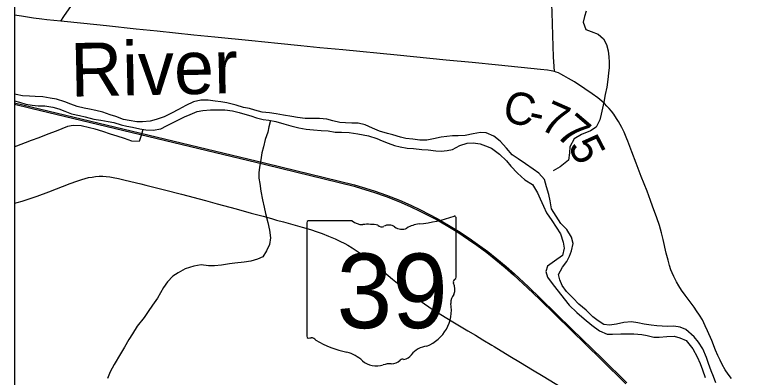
# Model space of a CAD drawing. Extents: x -7.5 to 53.5, y 0 to 22.
# Drawn here: x 2.1 to 3.39, y 17.82 to 18.461 of the extents above; entities that cross this region are included whole.
import ezdxf

# ---------------------------------------------------------------- set-up
doc = ezdxf.new("R2010")
doc.units = 0
for name, color, linetype in [('GM_X_Corporation', 7, 'Continuous'), ('GM_X_County_Road', 7, 'Continuous'), ('GM_X_County_Road_Text', 7, 'Continuous'), ('GM_X_Major_River', 7, 'Continuous'), ('GM_X_Major_River_Text', 7, 'Continuous'), ('GM_X_Minor_River', 7, 'Continuous'), ('GM_X_Rail_Line', 7, 'Continuous'), ('GM_X_State_Location', 7, 'Continuous'), ('GM_X_State_Route', 7, 'Continuous'), ('GM_X_State_Shield', 7, 'Continuous'), ('GM_X_Township_Road', 7, 'Continuous'), ('SH_Data', 7, 'Continuous')]:
    doc.layers.add(name, color=color, linetype=linetype)

msp = doc.modelspace()

# ---------------------------------------------------------------- linework, layer by layer
at = {"layer": 'GM_X_Corporation'}
msp.add_lwpolyline([(4.6087, 14.5302), (4.6021, 15.6139), (4.594, 15.8096), (4.5873, 16.3533), (4.5872, 16.3635), (4.5826, 16.8462), (4.5822, 16.8992), (4.577, 17.1178), (4.5749, 17.2575), (4.5771, 17.6201), (4.5718, 18.1276), (4.5696, 18.2604), (4.5565, 19.1354), (5.0411, 19.1401), (6.0424, 19.1527), (6.0433, 19.1527), (6.5522, 19.1561), (7.544, 19.1455), (8.414, 19.1709), (8.5159, 19.1718), (8.9, 19.1887), (8.9, 20.9), (2.1, 20.9), (2.1, 14.1)], dxfattribs=at)
at = {"layer": 'GM_X_County_Road'}
for points in [[(3.0531, 18.3609), (3.0527, 18.3697), (3.0516, 18.387), (3.0502, 18.4243), (3.0495, 18.446), (3.0491, 18.4647), (3.0481, 18.4957), (3.0475, 18.5174), (3.0463, 18.5516), (3.0457, 18.5827), (3.0453, 18.6044), (3.0449, 18.6137), (3.0444, 18.6167), (3.0437, 18.6196), (3.0427, 18.6224), (3.0412, 18.6249), (3.0393, 18.627), (3.037, 18.6288), (3.0361, 18.6293)], [(2.1814, 18.4499), (2.1571, 18.4524), (2.1481, 18.4534), (2.1333, 18.4552), (2.112, 18.4584), (2.1, 18.4606)], [(3.0531, 18.3609), (3.0472, 18.362), (3.0411, 18.363), (3.0288, 18.3647), (2.9545, 18.3721), (2.9082, 18.3768), (2.8618, 18.3812), (2.7752, 18.3896), (2.6794, 18.3991), (2.6391, 18.4029), (2.6051, 18.4062), (2.565, 18.4101), (2.5186, 18.4149), (2.4537, 18.4215), (2.4166, 18.425), (2.3517, 18.4319), (2.3146, 18.4358), (2.2621, 18.4415), (2.222, 18.4457), (2.1814, 18.4499)], [(3.0834, 18.3456), (3.078, 18.3487), (3.07, 18.3534), (3.0647, 18.3563), (3.0603, 18.3583), (3.0561, 18.36), (3.0531, 18.3609)], [(3.1827, 18.2375), (3.1809, 18.2421), (3.1762, 18.2536), (3.1722, 18.262), (3.1694, 18.2674), (3.1663, 18.2728), (3.163, 18.2781), (3.1578, 18.2857), (3.154, 18.2906), (3.15, 18.2954), (3.1458, 18.2999), (3.1415, 18.3043), (3.1369, 18.3084), (3.1297, 18.3142), (3.1196, 18.3215), (3.1068, 18.3302), (3.0888, 18.3424), (3.0834, 18.3456)], [(3.3657, 17.8181), (3.36, 17.8258), (3.3548, 17.8337), (3.3494, 17.8428), (3.3456, 17.8504), (3.3415, 17.8589), (3.3377, 17.8686), (3.3309, 17.8852), (3.3235, 17.9024), (3.3196, 17.9116), (3.3144, 17.9217), (3.3093, 17.9304), (3.3041, 17.9381), (3.2997, 17.9445), (3.2912, 17.9561), (3.2843, 17.9653), (3.2777, 17.9745), (3.2728, 17.982), (3.2686, 17.9891), (3.2643, 17.9983), (3.2609, 18.0053), (3.2588, 18.0106), (3.2564, 18.0182), (3.2538, 18.0272), (3.2507, 18.0399), (3.2453, 18.0639), (3.2422, 18.0758), (3.2387, 18.0888), (3.234, 18.1024), (3.2266, 18.1231), (3.2228, 18.133), (3.2167, 18.1492), (3.2066, 18.1752), (3.1978, 18.1986), (3.19, 18.2189), (3.1827, 18.2375)]]:
    msp.add_lwpolyline(points, dxfattribs=at)
at = {"layer": 'GM_X_Major_River'}
for points in [[(2.491, 18.3013), (2.4747, 18.3055), (2.4644, 18.3074), (2.4542, 18.3086), (2.4416, 18.3101), (2.4291, 18.3101), (2.4158, 18.3075), (2.4022, 18.3006), (2.3892, 18.2938), (2.3771, 18.287), (2.3642, 18.2805), (2.3501, 18.276), (2.3395, 18.2733), (2.3258, 18.2718), (2.316, 18.2722), (2.3023, 18.2741), (2.2924, 18.276), (2.2788, 18.2813), (2.2685, 18.2844), (2.2556, 18.2889), (2.2435, 18.292), (2.2325, 18.2943), (2.223, 18.2962), (2.2105, 18.2992), (2.1995, 18.3034), (2.1888, 18.3072), (2.174, 18.3117), (2.1627, 18.314), (2.1498, 18.3159), (2.1361, 18.3167), (2.1262, 18.3171), (2.1141, 18.3179), (2.1027, 18.3201), (2.1, 18.3211)], [(2.1, 18.309), (2.1087, 18.3068), (2.1201, 18.3034), (2.1311, 18.3011), (2.1414, 18.3004), (2.1532, 18.3), (2.1672, 18.2981), (2.1782, 18.295), (2.1888, 18.2909), (2.2006, 18.2859), (2.2146, 18.2829), (2.2245, 18.2806), (2.2397, 18.2768), (2.2522, 18.2749), (2.2651, 18.2726), (2.275, 18.2707), (2.2879, 18.2669), (2.2981, 18.2642), (2.308, 18.2627), (2.3213, 18.2593), (2.3319, 18.2578), (2.3448, 18.2574), (2.3581, 18.2596), (2.3683, 18.265), (2.3904, 18.276), (2.3999, 18.2805), (2.4097, 18.2851), (2.4223, 18.2904), (2.4321, 18.2919), (2.4458, 18.293), (2.4568, 18.2934), (2.4712, 18.2934), (2.4845, 18.2915), (2.4963, 18.2884), (2.5065, 18.2854), (2.5172, 18.2823), (2.527, 18.2789), (2.5388, 18.2759), (2.549, 18.2747), (2.5612, 18.2725), (2.5752, 18.2686), (2.5877, 18.2648), (2.6018, 18.2614), (2.6147, 18.2591), (2.628, 18.2576), (2.6412, 18.2568), (2.6534, 18.2561), (2.6663, 18.2538)], [(3.048, 18.1181), (3.0454, 18.1321), (3.0431, 18.1435), (3.0389, 18.1568), (3.0355, 18.1701), (3.0257, 18.1811), (3.0158, 18.1883), (3.0022, 18.1978), (2.9889, 18.2066), (2.9783, 18.2138), (2.9684, 18.2256), (2.9574, 18.2377), (2.946, 18.2464), (2.9328, 18.2522), (2.9229, 18.2529), (2.9096, 18.2506), (2.8956, 18.248), (2.883, 18.2469), (2.8732, 18.2469), (2.8629, 18.2461), (2.8534, 18.245), (2.8394, 18.2419), (2.828, 18.2397), (2.8155, 18.2397), (2.8033, 18.2412), (2.7908, 18.2427), (2.7813, 18.245), (2.768, 18.2488), (2.7582, 18.2515), (2.7441, 18.2553), (2.732, 18.2606), (2.7191, 18.2667), (2.7069, 18.2693), (2.6952, 18.2697), (2.6842, 18.2701), (2.6743, 18.2705), (2.6618, 18.2735), (2.6511, 18.2766), (2.6382, 18.2777), (2.6265, 18.2777), (2.6132, 18.2781), (2.5995, 18.2797), (2.5896, 18.2816), (2.5745, 18.2838), (2.5619, 18.2861), (2.5498, 18.2876), (2.5373, 18.2892), (2.5244, 18.2926), (2.5145, 18.2953), (2.5043, 18.2975), (2.491, 18.3013)], [(2.6663, 18.2538), (2.6773, 18.2538), (2.691, 18.253), (2.7058, 18.2507), (2.7156, 18.2488), (2.7251, 18.2469), (2.7395, 18.2424), (2.749, 18.2382), (2.7596, 18.234), (2.7707, 18.2302), (2.7805, 18.2275), (2.793, 18.2256), (2.8044, 18.2245), (2.8188, 18.2233), (2.8302, 18.2222), (2.8435, 18.2207), (2.853, 18.2199), (2.8636, 18.2214), (2.8731, 18.2229), (2.8864, 18.2301), (2.8993, 18.2343), (2.9096, 18.2351), (2.9221, 18.2328), (2.9316, 18.2294), (2.9418, 18.2252), (2.9563, 18.2149), (2.9684, 18.2028), (2.976, 18.1933), (2.9877, 18.1811), (3.001, 18.1697), (3.0146, 18.1614), (3.0234, 18.1465), (3.0279, 18.1359), (3.034, 18.123), (3.0393, 18.1112), (3.0487, 18.0975)], [(3.3381, 17.8108), (3.3338, 17.8217), (3.33, 17.8316), (3.3254, 17.8445), (3.3216, 17.8551), (3.3154, 17.8706), (3.3078, 17.8824), (3.2998, 17.8922), (3.285, 17.905), (3.2751, 17.9088), (3.2641, 17.9107), (3.2535, 17.9102), (3.2436, 17.9106), (3.2342, 17.9113), (3.2239, 17.9128), (3.2114, 17.9146), (3.2004, 17.9169), (3.189, 17.9183), (3.1758, 17.9171), (3.1629, 17.9144), (3.1504, 17.9125), (3.1402, 17.914), (3.1303, 17.92), (3.1208, 17.9272), (3.109, 17.9393), (3.0961, 17.9499), (3.0865, 17.9601), (3.0747, 17.9718), (3.0671, 17.9828), (3.0629, 17.9926), (3.0602, 18.0021), (3.0674, 18.015), (3.0749, 18.0249), (3.0798, 18.0344), (3.0835, 18.0439), (3.0861, 18.0568), (3.0831, 18.0682), (3.075, 18.0818), (3.0644, 18.0924), (3.048, 18.1181)], [(3.0487, 18.0975), (3.0641, 18.0742), (3.0687, 18.059), (3.0702, 18.0488), (3.0673, 18.0359), (3.0533, 18.0256), (3.0408, 18.0168), (3.0382, 18.0073), (3.0409, 17.9975), (3.0508, 17.9838), (3.0596, 17.9729), (3.0703, 17.9589), (3.0794, 17.9479), (3.0927, 17.935), (3.1056, 17.9237), (3.1193, 17.9124), (3.133, 17.9026), (3.1463, 17.8969), (3.1558, 17.8966), (3.1706, 17.8974), (3.1819, 17.8971), (3.1933, 17.8971), (3.2073, 17.896), (3.2172, 17.8942), (3.2289, 17.8915), (3.2384, 17.8916), (3.2517, 17.8928), (3.2649, 17.8932), (3.2748, 17.8902), (3.2858, 17.8853), (3.2976, 17.8706), (3.3053, 17.8565), (3.3106, 17.8448), (3.3148, 17.8338), (3.3194, 17.8198)]]:
    msp.add_lwpolyline(points, dxfattribs=at)
at = {"layer": 'GM_X_Minor_River'}
for points in [[(3.109, 18.4675), (3.106, 18.458), (3.1038, 18.4478), (3.1084, 18.4353), (3.1179, 18.4315), (3.1304, 18.427), (3.1399, 18.4187), (3.1453, 18.4085), (3.148, 18.3975), (3.1492, 18.3869), (3.15, 18.3774), (3.1496, 18.3679), (3.1489, 18.358), (3.1474, 18.3466), (3.146, 18.3333), (3.143, 18.32), (3.1404, 18.3064), (3.1382, 18.2961), (3.1359, 18.2855), (3.1333, 18.2756), (3.1266, 18.2623), (3.1167, 18.2558), (3.1012, 18.2493), (3.088, 18.242), (3.0801, 18.2276), (3.0798, 18.217), (3.0779, 18.2044), (3.0636, 18.1922), (3.0511, 18.1854)], [(2.5521, 18.2742), (2.549, 18.2633), (2.5471, 18.2539), (2.5425, 18.2406), (2.5395, 18.228), (2.5368, 18.217), (2.5349, 18.2045), (2.5326, 18.1916), (2.5315, 18.1817), (2.5314, 18.1722), (2.533, 18.1627), (2.5348, 18.1494), (2.5379, 18.1339), (2.5405, 18.121), (2.5428, 18.1099), (2.5473, 18.094), (2.5503, 18.0803), (2.5518, 18.067), (2.5499, 18.0549), (2.545, 18.0439), (2.5385, 18.0332), (2.5286, 18.0291), (2.5169, 18.0256), (2.5051, 18.0241), (2.4891, 18.0222), (2.4793, 18.0207), (2.4652, 18.0188), (2.4531, 18.0173), (2.4421, 18.0177), (2.4295, 18.0189), (2.4163, 18.0166), (2.4014, 18.012), (2.3889, 18.0048), (2.3794, 17.9991), (2.3699, 17.9893), (2.3627, 17.9794), (2.3577, 17.9699), (2.3524, 17.9604), (2.3437, 17.9479), (2.3361, 17.9365), (2.3285, 17.9259), (2.3163, 17.9107), (2.3079, 17.897), (2.3019, 17.8871), (2.2939, 17.8735), (2.287, 17.8621), (2.2756, 17.8431), (2.2688, 17.8302), (2.2642, 17.8184)], [(2.3265, 18.2585), (2.3243, 18.2498), (2.3201, 18.2369), (2.3068, 18.238), (2.2943, 18.2426), (2.281, 18.2468), (2.2692, 18.2502), (2.2556, 18.2551), (2.2423, 18.2589), (2.2321, 18.2616), (2.2176, 18.2646), (2.2036, 18.2654), (2.1933, 18.2635), (2.1831, 18.2593), (2.1732, 18.2552), (2.1584, 18.2502), (2.1425, 18.2438), (2.1292, 18.2389), (2.1185, 18.2347), (2.1033, 18.229), (2.1, 18.2279)]]:
    msp.add_lwpolyline(points, dxfattribs=at)
at = {"layer": 'GM_X_Rail_Line'}
for points in [[(2.1, 18.3057), (2.1292, 18.2986), (2.5434, 18.1986), (2.6999, 18.1603), (2.7134, 18.1565), (2.7346, 18.1498), (2.7566, 18.1421), (2.7794, 18.1333), (2.7994, 18.1245), (2.8169, 18.1163), (2.846, 18.1011), (2.8664, 18.0894), (2.8838, 18.0787), (2.9028, 18.0661), (2.9175, 18.0559), (2.9353, 18.0427), (2.9514, 18.03), (2.9679, 18.0162), (2.9827, 18.0033), (3.0073, 17.9803), (3.0283, 17.9599), (3.0842, 17.9052), (3.1372, 17.8534), (3.1811, 17.8104)], [(2.1, 18.3033), (2.1286, 18.2963), (2.5429, 18.1963), (2.6993, 18.1581), (2.7127, 18.1542), (2.7338, 18.1476), (2.7558, 18.1399), (2.7785, 18.1311), (2.7984, 18.1224), (2.8158, 18.1142), (2.8448, 18.0991), (2.8652, 18.0874), (2.8826, 18.0767), (2.9015, 18.0642), (2.9161, 18.054), (2.9339, 18.0409), (2.9499, 18.0282), (2.9663, 18.0144), (2.9811, 18.0015), (3.0057, 17.9786), (3.0266, 17.9582), (3.0826, 17.9035), (3.1356, 17.8517), (3.1794, 17.8087)]]:
    msp.add_lwpolyline(points, dxfattribs=at)
at = {"layer": 'GM_X_State_Route'}
msp.add_lwpolyline([(2.1, 18.1283), (2.1046, 18.1294), (2.1135, 18.1319), (2.1254, 18.1356), (2.14, 18.1408), (2.1603, 18.1484), (2.198, 18.163), (2.2097, 18.1672), (2.2186, 18.1701), (2.2246, 18.1718), (2.2307, 18.1733), (2.2369, 18.1744), (2.2431, 18.1752), (2.2493, 18.1756), (2.2556, 18.1756), (2.2618, 18.1753), (2.2681, 18.1747), (2.2742, 18.1737), (2.2834, 18.1719), (2.2955, 18.1691), (2.3226, 18.1622), (2.3316, 18.1599), (2.3436, 18.1569), (2.3648, 18.1517), (2.3948, 18.1439), (2.4369, 18.1328), (2.4579, 18.1272), (2.4911, 18.118), (2.5177, 18.1106), (2.5387, 18.1051), (2.5537, 18.101), (2.5627, 18.0984), (2.5746, 18.0951), (2.6075, 18.0859), (2.6224, 18.0815), (2.6342, 18.0777), (2.643, 18.0745), (2.6545, 18.07), (2.666, 18.065), (2.6745, 18.0611), (2.6828, 18.0569), (2.6883, 18.0539), (2.6963, 18.049), (2.7066, 18.042), (2.7166, 18.0347), (2.7289, 18.0251), (2.7482, 18.0095), (2.7674, 17.9937), (2.7818, 17.9818), (2.7915, 17.9741), (2.8013, 17.9665), (2.8113, 17.9592), (2.8239, 17.9502), (2.8393, 17.9397), (2.8524, 17.9314), (2.8736, 17.9185), (2.9003, 17.9025), (2.9136, 17.8946), (2.9269, 17.8866), (2.9428, 17.877), (2.9467, 17.8746), (2.9747, 17.8579), (2.9933, 17.8467), (3.0146, 17.8338), (3.0331, 17.8225), (3.0648, 17.8029)], dxfattribs=at)
at = {"layer": 'GM_X_State_Shield'}
for p, q in [((2.616, 18.0933), (2.616, 17.8932)), ((2.6958, 18.0968), (2.6186, 18.0968)), ((2.8797, 17.9971), (2.8797, 18.1017)), ((2.8796, 17.9971), (2.8797, 17.9971))]:
    msp.add_line(p, q, dxfattribs=at)
for centre, radius, start, end in [((2.7857, 18.3696), 0.2796, 275.8445, 288.9065), ((2.8767, 18.1022), 0.00294, 351.8621, 97.738), ((2.619, 18.0938), 0.00305, 98.1301, 188.1301), ((2.7142, 18.12), 0.0296, 231.6195, 271.1119), ((2.8214, 18.0357), 0.0563, 97.3462, 120.7689), ((2.724, 17.9844), 0.1064, 80.4867, 94.9883), ((2.7482, 18.0948), 0.00855, 219.7921, 297.1024), ((2.7607, 18.0717), 0.0178, 54.4667, 119.1411), ((2.7837, 18.1034), 0.0214, 233.8562, 294.8282), ((2.879, 17.9894), 0.00454, 107.944, 210.337), ((2.8765, 17.9967), 0.00314, 289.6038, 7.7341), ((2.8501, 17.9761), 0.0273, 340.033, 23.6496), ((2.8902, 17.9533), 0.0198, 136.8065, 186.9296), ((2.8014, 17.9399), 0.0699, 292.3089, 8.9858), ((2.6191, 17.8928), 0.00308, 171.9584, 258.3066), ((2.6195, 17.9133), 0.0235, 267.339, 280.6039), ((2.6243, 17.8817), 0.00848, 29.7484, 93.2717), ((2.7314, 18.0615), 0.2019, 240.4129, 257.1985), ((2.8309, 17.837), 0.0383, 94.4031, 142.5768), ((2.6712, 17.8033), 0.0632, 47.1842, 75.836), ((2.7824, 17.8738), 0.0226, 282.8732, 323.2771), ((2.7395, 17.8807), 0.0401, 230.7004, 286.2918), ((2.7656, 17.8657), 0.0214, 268.777, 315.5493), ((2.7849, 17.8463), 0.00601, 65.7517, 132.6484), ((2.7627, 17.8115), 0.0329, 85.6951, 111.2099)]:
    msp.add_arc(centre, radius, start, end, dxfattribs=at)
at = {"layer": 'GM_X_Township_Road'}
msp.add_lwpolyline([(2.1814, 18.4499), (2.187, 18.458), (2.2047, 18.4835)], dxfattribs=at)
at = {"layer": 'SH_Data'}
msp.add_line((2.1, 20.9), (2.1, 14.1), dxfattribs=at)

# ---------------------------------------------------------------- texts
at = {"layer": 'GM_X_County_Road_Text'}
for s, rotation, p in [('C', 347.4691, (2.9591, 18.2737)), ('7', 336.4037, (3.0247, 18.2594)), ('-', 347.4966, (3.0047, 18.2636)), ('7', 319.4608, (3.053, 18.2478)), ('5', 297.5007, (3.0761, 18.2295))]:
    msp.add_text(s, height=0.0568, rotation=rotation, dxfattribs=at).set_placement(p)
at = {"layer": 'GM_X_Major_River_Text'}
msp.add_text('River', height=0.09471, rotation=1.2412, dxfattribs=at).set_placement((2.1995, 18.3163))
at = {"layer": 'GM_X_State_Location'}
for s in ['s', 'r']:
    msp.add_text(s, height=0.000189, dxfattribs=at).set_placement((2.7449, 17.98))
msp.add_text('39', height=0.000189, rotation=0, dxfattribs=at).set_placement((2.6972, 17.9662))
at = {"layer": 'GM_X_State_Shield'}
msp.add_text('39', height=0.13184, dxfattribs=at).set_placement((2.6686, 17.9073))

doc.saveas('drawing.dxf')
